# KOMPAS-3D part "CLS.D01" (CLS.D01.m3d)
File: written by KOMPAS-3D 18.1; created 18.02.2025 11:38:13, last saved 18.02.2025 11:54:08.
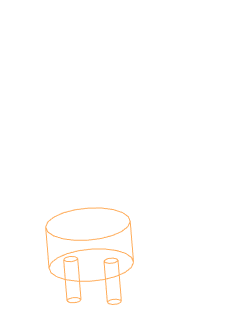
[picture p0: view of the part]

Document properties: Полное имя файла: Z:\Элхарт\БД\3D модели\ЭЛХАРТ\CLS.D01\CLS.D01.m3d

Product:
- Part/product: CLS.D01

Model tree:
1. Операция без истории:1
2. Операция без истории:2
3. Операция без истории:3
4. Операция без истории:4
5. Операция без истории:5
6. Операция без истории:6
7. Операция без истории:7
8. Операция без истории:8
9. Операция без истории:9
10. Условное изображение резьбы:1  (with: Операция без истории:1)  (labels: cil0_24705-2004 coarse; M4)
     Длина резьбы = 13; Шаг резьбы = 0.7; Номинальный диаметр резьбы = 4
11. Подгонка:1  (with: Операция без истории:1)
12. Условное изображение резьбы:2  (with: Операция без истории:3)  (labels: cil0_24705-2004 coarse; M4)
     Длина резьбы = 13; Шаг резьбы = 0.7; Номинальный диаметр резьбы = 4
13. Подгонка:2  (with: Операция без истории:3)
14. Условное изображение резьбы:3  (with: Операция без истории:9)
     Длина резьбы = 12.976; Шаг резьбы = 1.814; Номинальный диаметр резьбы = 26.441
15. Подгонка:3  (with: Операция без истории:9)

Expressions: cil2_6357-81; G 3/4
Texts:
  Точка начала. Х
  Точка начала. Y
  Точка начала. Z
